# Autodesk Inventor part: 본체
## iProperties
Created: 2015-01
Part Number: 본체
Material: 알루미늄-6061
Document SubType Name: Modeling
Designer: elite
Mass: 1021.17 g
Surface Area: 1059.8 cm^2
Volume: 376.814 cm^3
Density: 2.71 g/cm^3
Author: elite
